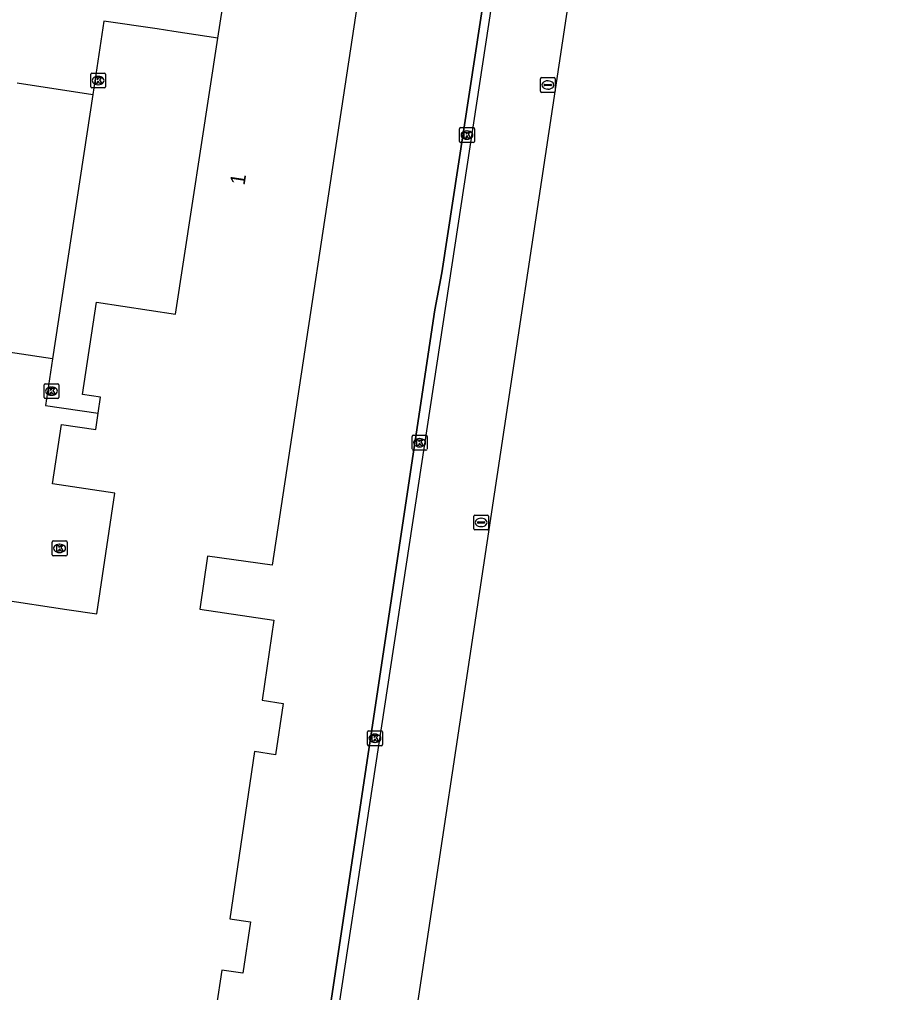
# Model space of a CAD drawing. Extents: x 161094 to 161705, y 379509 to 380907.
# Drawn here: x 161342.3 to 161400.8, y 380253.5 to 380319.1 of the extents above; entities that cross this region are included whole.
import ezdxf

# ---------------------------------------------------------------- set-up
doc = ezdxf.new("R2010")
doc.units = 0
for name, color, linetype in [('IMGEO_Hek', 7, 'Continuous'), ('IMGEO_Kolk', 7, 'Continuous'), ('IMGEO_Pand', 7, 'Continuous'), ('IMGEO_Pand_nummerreeks', 7, 'Continuous'), ('IMGEO_Pand_overbouw', 7, 'Continuous'), ('IMGEO_Terreindeel_open', 7, 'Continuous'), ('IMGEO_Voetpad_open', 7, 'Continuous'), ('IMGEO_Waterleidingput', 7, 'Continuous')]:
    doc.layers.add(name, color=color, linetype=linetype)

msp = doc.modelspace()

# ---------------------------------------------------------------- linework, layer by layer
at = {"layer": 'IMGEO_Hek'}
for points in [[(161379.666, 380360.168), (161370.769, 380302.037)], [(161370.769, 380302.037), (161370.307, 380299.553)], [(161370.307, 380299.553), (161362.86, 380250), (161361.584, 380241.511)]]:
    msp.add_lwpolyline(points, dxfattribs=at)
at = {"layer": 'IMGEO_Kolk'}
for p, q in [((161347.105, 380314.576), (161347.105, 380315.428)), ((161347.18, 380315.502), (161348.032, 380315.502)), ((161347.593, 380315.282), (161347.618, 380315.282)), ((161348.106, 380315.428), (161348.106, 380314.576)), ((161348.032, 380314.502), (161347.18, 380314.502)), ((161347.616, 380314.722), (161347.591, 380314.722)), ((161372.043, 380311.826), (161372.895, 380311.826)), ((161371.968, 380310.9), (161371.968, 380311.752)), ((161372.456, 380311.606), (161372.481, 380311.606)), ((161372.969, 380311.752), (161372.969, 380310.9)), ((161372.895, 380310.826), (161372.043, 380310.826)), ((161372.479, 380311.046), (161372.454, 380311.046)), ((161343.963, 380293.635), (161343.963, 380294.487)), ((161344.038, 380294.561), (161344.89, 380294.561)), ((161344.451, 380294.341), (161344.476, 380294.341)), ((161344.964, 380294.487), (161344.964, 380293.635)), ((161344.89, 380293.561), (161344.038, 380293.561)), ((161344.474, 380293.781), (161344.449, 380293.781)), ((161368.775, 380290.163), (161368.775, 380291.015)), ((161368.85, 380291.089), (161369.702, 380291.089)), ((161369.263, 380290.869), (161369.288, 380290.869)), ((161369.776, 380291.015), (161369.776, 380290.163)), ((161369.286, 380290.309), (161369.261, 380290.309)), ((161369.702, 380290.089), (161368.85, 380290.089)), ((161344.508, 380283.04), (161344.508, 380283.892)), ((161344.583, 380283.966), (161345.435, 380283.966)), ((161344.996, 380283.746), (161345.021, 380283.746)), ((161345.509, 380283.892), (161345.509, 380283.04)), ((161345.435, 380282.966), (161344.583, 380282.966)), ((161345.019, 380283.186), (161344.994, 380283.186)), ((161365.839, 380271.164), (161366.691, 380271.164)), ((161365.764, 380270.238), (161365.764, 380271.09)), ((161366.252, 380270.944), (161366.277, 380270.944)), ((161366.765, 380271.09), (161366.765, 380270.238)), ((161366.691, 380270.164), (161365.839, 380270.164)), ((161366.275, 380270.384), (161366.25, 380270.384))]:
    msp.add_line(p, q, dxfattribs=at)
for points in [[(161347.105, 380314.576), (161347.105, 380315.428)], [(161347.18, 380315.502), (161348.032, 380315.502)], [(161347.426, 380315.202), (161347.549, 380315.202), (161347.549, 380315.051), (161347.679, 380315.202), (161347.843, 380315.202), (161347.697, 380315.051), (161347.85, 380314.802), (161347.698, 380314.802), (161347.613, 380314.966), (161347.549, 380314.899), (161347.549, 380314.802), (161347.426, 380314.802), (161347.426, 380315.202)], [(161348.106, 380315.428), (161348.106, 380314.576)], [(161348.032, 380314.502), (161347.18, 380314.502)], [(161372.043, 380311.826), (161372.895, 380311.826)], [(161371.968, 380310.9), (161371.968, 380311.752)], [(161372.289, 380311.526), (161372.412, 380311.526), (161372.412, 380311.375), (161372.542, 380311.526), (161372.706, 380311.526), (161372.56, 380311.375), (161372.713, 380311.126), (161372.561, 380311.126), (161372.476, 380311.29), (161372.412, 380311.223), (161372.412, 380311.126), (161372.289, 380311.126), (161372.289, 380311.526)], [(161372.969, 380311.752), (161372.969, 380310.9)], [(161372.895, 380310.826), (161372.043, 380310.826)], [(161343.963, 380293.635), (161343.963, 380294.487)], [(161344.038, 380294.561), (161344.89, 380294.561)], [(161344.284, 380294.261), (161344.407, 380294.261), (161344.407, 380294.11), (161344.537, 380294.261), (161344.701, 380294.261), (161344.555, 380294.11), (161344.708, 380293.861), (161344.556, 380293.861), (161344.471, 380294.025), (161344.407, 380293.958), (161344.407, 380293.861), (161344.284, 380293.861), (161344.284, 380294.261)], [(161344.964, 380294.487), (161344.964, 380293.635)], [(161344.89, 380293.561), (161344.038, 380293.561)], [(161368.775, 380290.163), (161368.775, 380291.015)], [(161368.85, 380291.089), (161369.702, 380291.089)], [(161369.096, 380290.789), (161369.219, 380290.789), (161369.219, 380290.638), (161369.349, 380290.789), (161369.513, 380290.789), (161369.367, 380290.638), (161369.52, 380290.389), (161369.368, 380290.389), (161369.283, 380290.553), (161369.219, 380290.486), (161369.219, 380290.389), (161369.096, 380290.389), (161369.096, 380290.789)], [(161369.776, 380291.015), (161369.776, 380290.163)], [(161369.702, 380290.089), (161368.85, 380290.089)], [(161344.508, 380283.04), (161344.508, 380283.892)], [(161344.583, 380283.966), (161345.435, 380283.966)], [(161344.829, 380283.666), (161344.952, 380283.666), (161344.952, 380283.515), (161345.082, 380283.666), (161345.246, 380283.666), (161345.1, 380283.515), (161345.253, 380283.266), (161345.101, 380283.266), (161345.016, 380283.43), (161344.952, 380283.363), (161344.952, 380283.266), (161344.829, 380283.266), (161344.829, 380283.666)], [(161345.509, 380283.892), (161345.509, 380283.04)], [(161345.435, 380282.966), (161344.583, 380282.966)], [(161365.839, 380271.164), (161366.691, 380271.164)], [(161365.764, 380270.238), (161365.764, 380271.09)], [(161366.085, 380270.864), (161366.208, 380270.864), (161366.208, 380270.713), (161366.338, 380270.864), (161366.502, 380270.864), (161366.356, 380270.713), (161366.509, 380270.464), (161366.357, 380270.464), (161366.272, 380270.628), (161366.208, 380270.561), (161366.208, 380270.464), (161366.085, 380270.464), (161366.085, 380270.864)], [(161366.765, 380271.09), (161366.765, 380270.238)], [(161366.691, 380270.164), (161365.839, 380270.164)]]:
    msp.add_lwpolyline(points, dxfattribs=at)
for centre, start, end in [((161347.182, 380315.426), 91.55205, 178.44795), ((161347.182, 380315.426), 91.55205, 178.44795), ((161348.03, 380315.426), 1.55205, 88.44795), ((161348.03, 380315.426), 1.55205, 88.44795), ((161347.182, 380314.578), 181.55205, 268.44795), ((161347.182, 380314.578), 181.55205, 268.44795), ((161348.03, 380314.578), 271.55205, 358.44795), ((161348.03, 380314.578), 271.55205, 358.44795), ((161372.045, 380311.75), 91.55205, 178.44795), ((161372.045, 380311.75), 91.55205, 178.44795), ((161372.893, 380311.75), 1.55205, 88.44795), ((161372.893, 380311.75), 1.55205, 88.44795), ((161372.045, 380310.902), 181.55205, 268.44795), ((161372.045, 380310.902), 181.55205, 268.44795), ((161372.893, 380310.902), 271.55205, 358.44795), ((161372.893, 380310.902), 271.55205, 358.44795), ((161344.04, 380294.485), 91.55205, 178.44795), ((161344.04, 380294.485), 91.55205, 178.44795), ((161344.888, 380294.485), 1.55205, 88.44795), ((161344.888, 380294.485), 1.55205, 88.44795), ((161344.04, 380293.637), 181.55205, 268.44795), ((161344.04, 380293.637), 181.55205, 268.44795), ((161344.888, 380293.637), 271.55205, 358.44795), ((161344.888, 380293.637), 271.55205, 358.44795), ((161368.852, 380291.013), 91.55205, 178.44795), ((161368.852, 380291.013), 91.55205, 178.44795), ((161369.7, 380291.013), 1.55205, 88.44795), ((161369.7, 380291.013), 1.55205, 88.44795), ((161368.852, 380290.165), 181.55205, 268.44795), ((161368.852, 380290.165), 181.55205, 268.44795), ((161369.7, 380290.165), 271.55205, 358.44795), ((161369.7, 380290.165), 271.55205, 358.44795), ((161344.585, 380283.89), 91.55205, 178.44795), ((161344.585, 380283.89), 91.55205, 178.44795), ((161345.433, 380283.89), 1.55205, 88.44795), ((161345.433, 380283.89), 1.55205, 88.44795), ((161344.585, 380283.042), 181.55205, 268.44795), ((161344.585, 380283.042), 181.55205, 268.44795), ((161345.433, 380283.042), 271.55205, 358.44795), ((161345.433, 380283.042), 271.55205, 358.44795), ((161365.841, 380271.088), 91.55205, 178.44795), ((161365.841, 380271.088), 91.55205, 178.44795), ((161366.689, 380271.088), 1.55205, 88.44795), ((161366.689, 380271.088), 1.55205, 88.44795), ((161365.841, 380270.24), 181.55205, 268.44795), ((161365.841, 380270.24), 181.55205, 268.44795), ((161366.689, 380270.24), 271.55205, 358.44795), ((161366.689, 380270.24), 271.55205, 358.44795)]:
    msp.add_arc(centre, 0.0765, start, end, dxfattribs=at)
for centre, major_axis, ratio, start_param, end_param in [((161347.592, 380315.002), (-0.387, 0.002), 0.722429, 4.712389, 7.853982), ((161347.617, 380315.002), (-0.39, 0.002), 0.717154, 1.570796, 4.712389), ((161372.455, 380311.326), (-0.387, 0.002), 0.722429, 4.712389, 7.853982), ((161372.48, 380311.326), (-0.39, 0.002), 0.717154, 1.570796, 4.712389), ((161344.45, 380294.061), (-0.387, 0.002), 0.722429, 4.712389, 7.853982), ((161344.475, 380294.061), (-0.39, 0.002), 0.717154, 1.570796, 4.712389), ((161369.262, 380290.589), (-0.387, 0.002), 0.722429, 4.712389, 7.853982), ((161369.287, 380290.589), (-0.39, 0.002), 0.717154, 1.570796, 4.712389), ((161344.995, 380283.466), (-0.387, 0.002), 0.722429, 4.712389, 7.853982), ((161345.02, 380283.466), (-0.39, 0.002), 0.717154, 1.570796, 4.712389), ((161366.251, 380270.664), (-0.387, 0.002), 0.722429, 4.712389, 7.853982), ((161366.276, 380270.664), (-0.39, 0.002), 0.717154, 1.570796, 4.712389)]:
    msp.add_ellipse(centre, major_axis=major_axis, ratio=ratio, start_param=start_param, end_param=end_param, dxfattribs=at)
at = {"layer": 'IMGEO_Pand'}
for points in [[(161341.066, 380280.007), (161345.507, 380279.345), (161347.51, 380279.046), (161348.74, 380287.188), (161346.771, 380287.484), (161344.529, 380287.821), (161345.133, 380291.822), (161347.454, 380291.469), (161347.619, 380292.588), (161347.776, 380293.654), (161346.549, 380293.841), (161347.498, 380300.059), (161352.828, 380299.261), (161355.684, 380317.859), (161356.465, 380322.943), (161356.506, 380323.21)], [(161356.506, 380323.21), (161364.28, 380322.059), (161365.327, 380321.904), (161359.341, 380282.327), (161354.975, 380282.94), (161354.457, 380279.373), (161359.454, 380278.62), (161358.672, 380273.226), (161360.076, 380273.013), (161359.554, 380269.552), (161358.142, 380269.766), (161356.483, 380258.492), (161357.868, 380258.285), (161357.354, 380254.827), (161355.945, 380255.037), (161355.189, 380250), (161354.579, 380245.935), (161355.992, 380245.722), (161355.502, 380242.474)], [(161342.154, 380314.837), (161347.246, 380314.062), (161344.534, 380296.237), (161339.423, 380297.015), (161339.843, 380299.782), (161339.881, 380300.03), (161338.893, 380300.18), (161340.646, 380311.385)]]:
    msp.add_lwpolyline(points, dxfattribs=at)
at = {"layer": 'IMGEO_Pand_overbouw'}
msp.add_lwpolyline([(161355.684, 380317.859), (161352.709, 380318.314), (161351.585, 380318.483), (161347.998, 380319.005), (161347.246, 380314.062), (161344.534, 380296.237), (161344.057, 380293.103), (161347.619, 380292.588), (161347.776, 380293.654), (161346.549, 380293.841), (161347.498, 380300.059), (161352.828, 380299.261)], close=True, dxfattribs=at)
at = {"layer": 'IMGEO_Terreindeel_open'}
for points in [[(161379.665, 380356.51), (161363.43, 380250), (161362.621, 380244.695)], [(161449.975, 380341.416), (161384, 380351.548), (161368.719, 380250), (161368.518, 380248.665), (161434.571, 380238.556), (161436.285, 380250), (161449.975, 380341.416)]]:
    msp.add_lwpolyline(points, dxfattribs=at)
at = {"layer": 'IMGEO_Voetpad_open'}
msp.add_lwpolyline([(161361.584, 380241.511), (161362.86, 380250), (161370.307, 380299.553), (161370.769, 380302.037), (161379.666, 380360.168)], dxfattribs=at)
at = {"layer": 'IMGEO_Waterleidingput'}
for p, q in [((161377.422, 380314.274), (161377.422, 380315.126)), ((161377.497, 380315.2), (161378.349, 380315.2)), ((161378.423, 380315.126), (161378.423, 380314.274)), ((161377.681, 380314.694), (161377.681, 380314.706)), ((161378.119, 380314.657), (161377.721, 380314.657)), ((161377.724, 380314.743), (161378.122, 380314.743)), ((161377.933, 380314.42), (161377.908, 380314.42)), ((161377.91, 380314.98), (161377.935, 380314.98)), ((161378.165, 380314.706), (161378.165, 380314.694)), ((161378.349, 380314.2), (161377.497, 380314.2)), ((161372.923, 380284.784), (161372.923, 380285.636)), ((161372.998, 380285.71), (161373.85, 380285.71)), ((161373.924, 380285.636), (161373.924, 380284.784)), ((161373.182, 380285.204), (161373.182, 380285.216)), ((161373.62, 380285.167), (161373.222, 380285.167)), ((161373.225, 380285.253), (161373.623, 380285.253)), ((161373.434, 380284.93), (161373.409, 380284.93)), ((161373.411, 380285.49), (161373.436, 380285.49)), ((161373.666, 380285.216), (161373.666, 380285.204)), ((161373.85, 380284.71), (161372.998, 380284.71))]:
    msp.add_line(p, q, dxfattribs=at)
for points in [[(161377.422, 380314.274), (161377.422, 380315.126)], [(161377.497, 380315.2), (161378.349, 380315.2)], [(161378.423, 380315.126), (161378.423, 380314.274)], [(161378.349, 380314.2), (161377.497, 380314.2)], [(161372.923, 380284.784), (161372.923, 380285.636)], [(161372.998, 380285.71), (161373.85, 380285.71)], [(161373.924, 380285.636), (161373.924, 380284.784)], [(161373.85, 380284.71), (161372.998, 380284.71)]]:
    msp.add_lwpolyline(points, dxfattribs=at)
for centre, radius, start, end in [((161377.499, 380315.124), 0.0765, 91.55205, 178.44795), ((161377.499, 380315.124), 0.0765, 91.55205, 178.44795), ((161378.347, 380315.124), 0.0765, 1.55205, 88.44795), ((161378.347, 380315.124), 0.0765, 1.55205, 88.44795), ((161377.721, 380314.703), 0.0403, 85.87752, 175.75265), ((161377.718, 380314.693), 0.0366, 178.93798, 274.71019), ((161378.122, 380314.7), 0.043, 264.86636, 352.45326), ((161378.126, 380314.705), 0.0386, 1.73085, 96.63898), ((161377.499, 380314.276), 0.0765, 181.55205, 268.44795), ((161377.499, 380314.276), 0.0765, 181.55205, 268.44795), ((161378.347, 380314.276), 0.0765, 271.55205, 358.44795), ((161378.347, 380314.276), 0.0765, 271.55205, 358.44795), ((161373, 380285.634), 0.0765, 91.55205, 178.44795), ((161373, 380285.634), 0.0765, 91.55205, 178.44795), ((161373.848, 380285.634), 0.0765, 1.55205, 88.44795), ((161373.848, 380285.634), 0.0765, 1.55205, 88.44795), ((161373.222, 380285.213), 0.0403, 85.87752, 175.75265), ((161373.219, 380285.203), 0.0366, 178.93798, 274.71019), ((161373.623, 380285.21), 0.043, 264.86636, 352.45326), ((161373.627, 380285.215), 0.0386, 1.73085, 96.63898), ((161373, 380284.786), 0.0765, 181.55205, 268.44795), ((161373, 380284.786), 0.0765, 181.55205, 268.44795), ((161373.848, 380284.786), 0.0765, 271.55205, 358.44795), ((161373.848, 380284.786), 0.0765, 271.55205, 358.44795)]:
    msp.add_arc(centre, radius, start, end, dxfattribs=at)
for centre, major_axis, ratio, start_param, end_param in [((161377.909, 380314.7), (-0.387, 0.002), 0.722429, 4.712389, 7.853982), ((161377.934, 380314.7), (-0.39, 0.002), 0.717154, 1.570796, 4.712389), ((161373.41, 380285.21), (-0.387, 0.002), 0.722429, 4.712389, 7.853982), ((161373.435, 380285.21), (-0.39, 0.002), 0.717154, 1.570796, 4.712389)]:
    msp.add_ellipse(centre, major_axis=major_axis, ratio=ratio, start_param=start_param, end_param=end_param, dxfattribs=at)

# ---------------------------------------------------------------- texts
at = {"layer": 'IMGEO_Pand_nummerreeks'}
msp.add_text('1', height=1, rotation=81.26833, dxfattribs=at).set_placement((161357.474, 380307.903))

doc.saveas('drawing.dxf')
